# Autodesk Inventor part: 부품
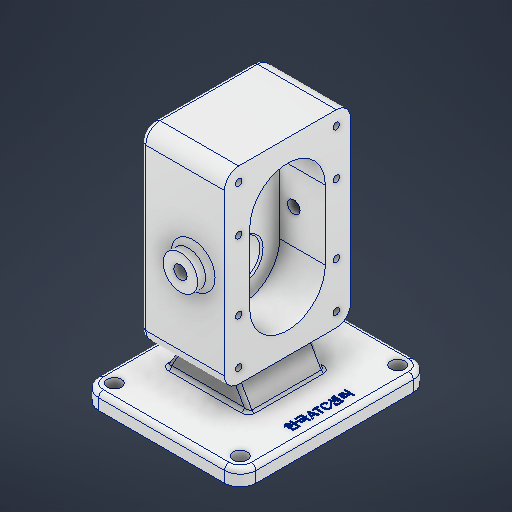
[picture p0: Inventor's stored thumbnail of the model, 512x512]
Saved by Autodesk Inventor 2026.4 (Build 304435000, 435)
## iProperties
Created: 2026-10
Part Number: 부품
Material: 알루미늄 6061
Document SubType Name: Modeling
Designer: user
Density: 2.7 g/cm^3
Appearance: 알루미늄 - 평지
Mass: 1471.26 g
Surface Area: 821.751 cm^2
Volume: 544.911 cm^3
Author: user
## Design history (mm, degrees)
sketch "스케치1"
  geometry: L1 (50, 60)-(-50, 60); L2 (-50, 60)-(-50, -60); L3 (-50, -60)-(50, -60); L4 (50, -60)-(50, 60); L5 (50, 60)-(-50, -60); L6 (-50, 60)-(50, -60); 1 further point
  constraints: 12 end point, 2 midpoint, 2 parallel, 1 horizontal, 1 perpendicular
  dimensions: "d0" = 100 distance of L3.end L2.end; "d1" = 120 distance of L2.end L1.end
extrude "돌출1" new body sketch "스케치1" distance "d2" = 10; taper "d3" = 0 deg
sketch "스케치3"
  geometry: L1 (-33, 30)-(20, 30); L2 (20, 30)-(20, 150); L3 (20, 150)-(-33, 150); L4 (-33, 150)-(-33, 30); L5 (-33, 30)-(20, 150); L6 (20, 30)-(-33, 150); L7 (50, 0)-(-50, 0) reference; L8 (50, 10)-(-50, 10) reference; L9 (-33, 10)-(-16.996, 37.719); L10 (20, 10)-(5.255, 35.539); L11 (-50, 0)-(-50, 10) reference; L12 (20, 10)-(-33, 10); 7 further points
  constraints: 18 end point, 5 midpoint, 2 parallel, 2 point on line, 1 collinear, 1 horizontal, 1 perpendicular, 1 vertical alignment
  dimensions: "d5" = 53 distance of L2.end L3.end; "d6" = 120 distance of L3.end L1.start; "d7" = 150 distance between parallel lines of L7 L3; "d16" = 60 deg angle of L8 L10; "d17" = 17 horizontal distance of point (-50, 5) L9.start; "d18" = 53 distance of L10.start L9.start; "d19" = 60 deg angle of L8 L9
extrude "돌출2" join sketch "스케치3" stored distance "d8" = 80; taper "d9" = 0 deg
sketch "스케치4"
  geometry: L1 (40, 82)-(40, 38); L2 (16, 82)-(16, 38); L3 (64, 38)-(64, 82); L4 (-20, -30)-(100, -30) reference; A1 r 24 centre (40, 82) between (64, 82) and (16, 82); A2 r 24 centre (40, 38) between (16, 38) and (64, 38); 4 further points
  constraints: 8 end point, 4 point on circle, 4 tangent, 3 midpoint, 2 centre point, 1 parallel, 1 vertical, 1 vertical alignment
  dimensions: "d10" = 48 distance between parallel lines of L3 L2; "d11" = 90 distance of point (40, -30) point (40, 60); "d12" = 44 distance of L1.end L1.start
extrude "돌출3" cut sketch "스케치4" distance "d13" = 29; taper "d14" = 0 deg
sketch "스케치5"
  geometry: 1 further point
extrude "돌출4" join sketch "스케치3" stored distance "d20" = 48; taper "d21" = 0 deg
sketch "스케치6"
  geometry: L1 (20, 136)-(20, 112) reference; L2 (20, 68)-(20, 44) reference; L3 (20, 112)-(-50, 112); L4 (20, 68)-(-9, 68) reference; L5 (20, 68)-(-33, 68); L6 (-9, 124.5)-(-24, 124.5); L7 (-24, 124.5)-(-24, 120.5); L8 (-24, 120.5)-(-42.7, 120.5); L9 (-33, 150)-(-33, 30) reference; L10 (-9, 136)-(-9, 112) reference; L11 (20, 30)-(20, 150) reference; L12 (-42.7, 120.5)-(-42.7, 125.5); L13 (-43.2, 126)-(-50, 126); L14 (-50, 131)-(-33, 131); L15 (-50, 131)-(-50, 112); L16 (-9, 124.5)-(-9, 112); L17 (-50, 112)-(-9, 112); L18 (-9, 68)-(-9, 112) reference; L19 (-9, 80.5)-(-24, 80.5); L20 (-24, 80.5)-(-24, 68); L21 (-24, 68)-(-9, 68); L22 (-9, 68)-(-9, 44) reference; L23 (-9, 68)-(-9, 80.5); A1 r 0.5 centre (-43.2, 125.5) between (-42.7, 125.5) and (-43.2, 126); 5 further points
  constraints: 30 end point, 10 point on line, 7 perpendicular, 3 collinear, 2 horizontal, 2 point on circle, 2 tangent, 2 vertical, 1 centre point
  dimensions: "d22" = 25 diameter of L6 L3; "d23" = 15 distance of L6.start L6.end; "d24" = 17 diameter of L8 L3; "d26" = 28 diameter of L13 L3; "d27" = 38 diameter of L14 L3; "d28" = 70 distance between parallel lines of L11 L15; "d29" = 7.3 distance of point (-42.7, 126) L13.end; "d30" = 0.5 radius of A1; "d33" = 25 diameter of L19 L5; "d34" = 15 distance of L19.start L19.end
revolve "회전1" stored, may be unused: angle "d31" = 90 deg
revolve "회전2" stored, may be unused: angle "d32" = 90 deg
revolve "회전3" stored, may be unused: angle "d35" = 90 deg
chamfer "모따기1" distance "d36" = 1; stored, may be unused: second distance "d37" = 2, angle "d38" = 45 deg
chamfer "모따기2" distance "d39" = 0.7; stored, may be unused: second distance "d40" = 2, angle "d41" = 30 deg
chamfer "모따기3" distance "d42" = 1; stored, may be unused: second distance "d43" = 2, angle "d44" = 30 deg
sketch "스케치8"
  geometry: L1 (-50, 0)-(50, 0) reference; L2 (-20, 150)-(-20, 30) reference; C1 r 11 at (0, 90); 4 further points
  constraints: 3 midpoint, 2 vertical alignment, 1 centre point, 1 horizontal alignment
  dimensions: "d45" = 22 diameter of C1
extrude "돌출5" join sketch "스케치8" distance "d46" = 8; taper "d47" = 0 deg
sketch "스케치9"
  geometry: C1 r 11 at (0, 0) reference; 2 further points
  constraints: 1 coincident
hole "구멍1" sketch "스케치9" at (0, 0) diameter "d48" = 8; stored, may be unused: countersink angle "d54" = 90 deg, drill point angle "d56" = 0 deg; dims "d49" = 7.4, "d50" = 0.62479, "d51" = 7.985, "d52" = 4, "d53" = 2, "d55" = 11.9
sketch "스케치10"
  geometry: C1 r 11 at (0, 0) reference; 2 further points
  constraints: 1 coincident
hole "구멍2" sketch "스케치10" at (0, 0) diameter "d57" = 8; stored, may be unused: countersink angle "d63" = 90 deg, drill point angle "d65" = 0 deg; dims "d58" = 7.4, "d59" = 0.62479, "d60" = 7.985, "d61" = 4, "d62" = 2, "d64" = 8
fillet "모깎기1" dims "d66" = 3
sketch "스케치11"
  geometry: L1 (9, 9)-(71, 9); L2 (71, 9)-(71, 111); L3 (71, 111)-(9, 111); L4 (9, 111)-(9, 9); L5 (9, 9)-(71, 111); L6 (71, 9)-(9, 111); L7 (-20, -30)-(100, -30) reference; L8 (64, 82)-(64, 38) reference; L9 (9, 38)-(71, 38); L10 (71, 38)-(71, 82); L11 (71, 82)-(9, 82); L12 (9, 82)-(9, 38); L13 (9, 38)-(71, 82); L14 (71, 38)-(9, 82); 4 further points
  constraints: 24 end point, 6 midpoint, 4 parallel, 2 horizontal, 2 perpendicular, 1 horizontal alignment, 1 point on line, 1 vertical alignment
  dimensions: "d67" = 62 distance of L2.end L3.end; "d68" = 44 distance between parallel lines of L9 L11; "d69" = 29 distance between parallel lines of L11 L3
hole "구멍3" sketch "스케치11" at (9, 111), (71, 111), (9, 82), (71, 82), (71, 38), (9, 38), (71, 9), (9, 9) diameter "d70" = 4.134; stored, may be unused: countersink angle "d74" = 90 deg, drill point angle "d76" = 118 deg; dims "d71" = 10, "d72" = 4, "d73" = 2, "d75" = 12
fillet "모깎기2" dims "d77" = 10
sketch "스케치13"
  geometry: A1 r 10 centre (40, -50) between (40, -60) and (50, -50) reference; A2 r 10 centre (40, 50) between (50, 50) and (40, 60) reference; A3 r 10 centre (-40, 50) between (-40, 60) and (-50, 50) reference; A4 r 10 centre (-40, -50) between (-50, -50) and (-40, -60) reference; 5 further points
  constraints: 4 coincident
hole "구멍4" sketch "스케치13" at (40, -50), (40, 50), (-40, 50), (-40, -50) diameter "d78" = 9; stored, may be unused: countersink angle "d82" = 90 deg, drill point angle "d84" = 0 deg; dims "d79" = 10, "d80" = 4, "d81" = 2, "d83" = 9
fillet "모깎기3" dims "d85" = 3
fillet "모깎기4" dims "d86" = 2
fillet "모깎기5" dims "d87" = 9
fillet "모깎기6" dims "d88" = 3
sketch "스케치14" dims "d0" = 100, "d1" = 120
  geometry: L1 (50, -50)-(50, 50) reference; 3 further points
  constraints: 1 horizontal alignment, 1 midpoint, 1 other
  dimensions: "d89" = 10 distance from line of L1 point (40, 0)
feature "엠보싱1" sketch "스케치14" dims "d0" = 100, "d1" = 120, "d90" = 0.5, "d91" = 0
feature "ў耀Ѡ耀Ѣ耀Ѥ耀Ѧ耀Ѩ耀Ѫ耀Ѭ耀" dims "d0" = 100, "d1" = 120, "d2" = 10, "d3" = 0, "d5" = 53, "d6" = 120, "d7" = 150, "d8" = 80, "d9" = 0, "d10" = 48, "d11" = 90, "d12" = 44, "d13" = 29, "d14" = 0, "d16" = 60 deg, "d17" = 17, "d18" = 53, "d19" = 60 deg, "d20" = 48, "d21" = 0, "d22" = 25, "d23" = 15, "d24" = 17, "d26" = 28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
node "솔리드1"
mirror "미러1"
